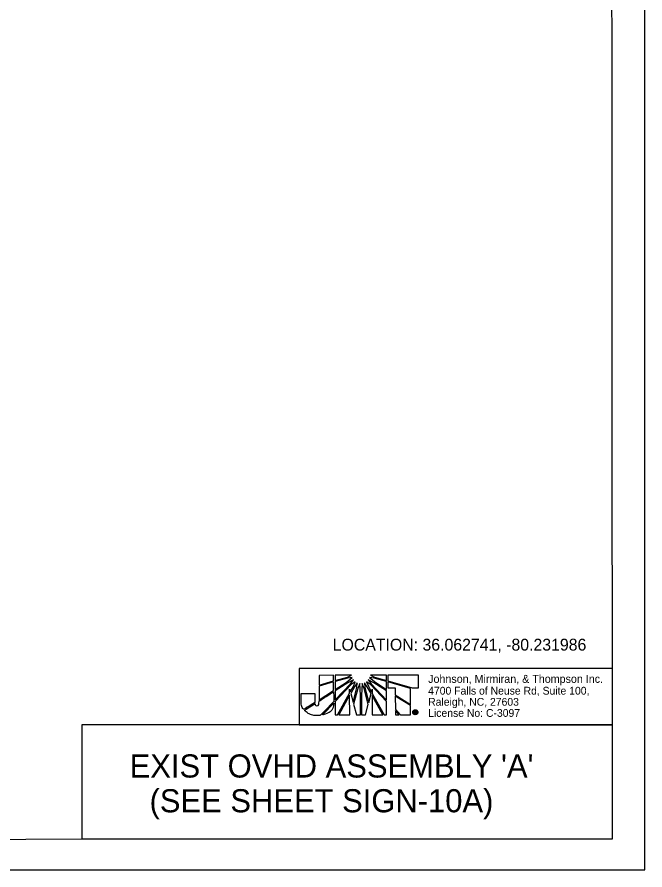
# Model space of a CAD drawing. Extents: x 1726790 to 1728895, y 539219 to 541550.
# Drawn here: x 1727517.9 to 1727598.1, y 539383.1 to 539492 of the extents above; entities that cross this region are included whole.
import ezdxf

# ---------------------------------------------------------------- set-up
doc = ezdxf.new("R2010")
doc.units = 0
for name, color, linetype in [('Default', 7, 'Continuous'), ('DEV BORDER CELL', 7, 'Continuous'), ('Overhead Sheet Border', 7, 'Continuous'), ('Overhead Sheet Box', 7, 'Continuous'), ('Overhead Sheet Text', 7, 'Continuous'), ('Sheet Plot Border Outside CELL', 7, 'Continuous'), ('Sheet Sticker Exception Certification CELL', 7, 'Continuous')]:
    doc.layers.add(name, color=color, linetype=linetype)

msp = doc.modelspace()

# ---------------------------------------------------------------- linework, layer by layer
at = {"layer": 'Default'}
for p, q in [((1727558.32, 539407.99), (1727556.45, 539407.98)), ((1727556.45, 539407.98), (1727556.45, 539406.74)), ((1727558.32, 539407.26), (1727558.32, 539407.99)), ((1727560.62, 539408), (1727558.52, 539408)), ((1727558.52, 539408), (1727558.52, 539407.33)), ((1727558.52, 539407.33), (1727560.09, 539407.76)), ((1727560.09, 539407.61), (1727558.52, 539407.18)), ((1727559.92, 539407.06), (1727560.7, 539407.69)), ((1727560.09, 539407.76), (1727560.62, 539408)), ((1727560.7, 539407.69), (1727560.09, 539407.61)), ((1727562.9, 539407.69), (1727563.69, 539407.05)), ((1727563.48, 539407.62), (1727562.9, 539407.69)), ((1727565.09, 539407.99), (1727563.01, 539408)), ((1727563.01, 539408), (1727563.53, 539407.75)), ((1727565.09, 539407.18), (1727563.48, 539407.62)), ((1727563.53, 539407.75), (1727565.09, 539407.32)), ((1727565.09, 539407.32), (1727565.09, 539407.99)), ((1727569.17, 539408.01), (1727565.23, 539408)), ((1727565.23, 539408), (1727565.23, 539407.28)), ((1727569.17, 539406.39), (1727569.17, 539408.01)), ((1727556.45, 539406.74), (1727558.32, 539407.26)), ((1727558.32, 539407.13), (1727556.45, 539406.6)), ((1727556.45, 539406.6), (1727556.45, 539404.85)), ((1727558.32, 539406.04), (1727558.32, 539407.13)), ((1727558.52, 539407.18), (1727558.52, 539406.17)), ((1727558.52, 539406.17), (1727559.92, 539407.06)), ((1727560.14, 539407.04), (1727558.52, 539406)), ((1727558.52, 539404.84), (1727560.49, 539406.89)), ((1727560.57, 539406.79), (1727558.52, 539404.64)), ((1727560.85, 539407.4), (1727560.14, 539407.04)), ((1727560.45, 539405.86), (1727560.84, 539406.57)), ((1727560.49, 539406.89), (1727560.85, 539407.4)), ((1727560.97, 539406.53), (1727560.5, 539405.68)), ((1727561.07, 539407.17), (1727560.57, 539406.79)), ((1727560.84, 539406.57), (1727561.07, 539407.17)), ((1727561.34, 539407.01), (1727560.97, 539406.53)), ((1727561.29, 539406.43), (1727561.34, 539407.01)), ((1727561.65, 539406.92), (1727561.39, 539406.32)), ((1727561.73, 539405.45), (1727561.65, 539406.92)), ((1727561.96, 539406.92), (1727561.86, 539405.45)), ((1727562.2, 539406.32), (1727561.96, 539406.92)), ((1727562.26, 539407.01), (1727562.32, 539406.41)), ((1727562.62, 539406.53), (1727562.26, 539407.01)), ((1727562.52, 539407.17), (1727562.75, 539406.58)), ((1727563.02, 539406.79), (1727562.52, 539407.17)), ((1727563.1, 539405.65), (1727562.62, 539406.53)), ((1727562.74, 539407.4), (1727563.1, 539406.88)), ((1727563.46, 539407.04), (1727562.74, 539407.4)), ((1727562.75, 539406.58), (1727563.15, 539405.83)), ((1727565.08, 539404.62), (1727563.02, 539406.79)), ((1727563.1, 539406.88), (1727565.08, 539404.82)), ((1727565.07, 539406.02), (1727563.46, 539407.04)), ((1727563.69, 539407.05), (1727565.07, 539406.19)), ((1727565.07, 539406.19), (1727565.09, 539407.18)), ((1727565.23, 539407.28), (1727565.23, 539407.26)), ((1727565.23, 539407.26), (1727568.33, 539406.39)), ((1727565.23, 539407.15), (1727565.23, 539407.13)), ((1727568.13, 539406.32), (1727565.23, 539407.15)), ((1727565.23, 539407.13), (1727565.23, 539406.38)), ((1727556.45, 539404.85), (1727558.32, 539406.04)), ((1727558.52, 539406), (1727558.52, 539404.84)), ((1727558.83, 539402.94), (1727560.36, 539405.7)), ((1727560.36, 539405.44), (1727558.98, 539402.94)), ((1727560.36, 539405.7), (1727560.36, 539406.2)), ((1727560.36, 539406.2), (1727560.45, 539405.86)), ((1727560.37, 539402.94), (1727560.36, 539405.44)), ((1727560.5, 539405.68), (1727560.8, 539404.56)), ((1727560.8, 539404.56), (1727561.29, 539406.43)), ((1727561.39, 539406.32), (1727560.87, 539404.3)), ((1727561.73, 539402.95), (1727561.73, 539405.45)), ((1727561.86, 539405.45), (1727561.86, 539402.95)), ((1727562.74, 539404.27), (1727562.2, 539406.32)), ((1727562.32, 539406.41), (1727562.81, 539404.52)), ((1727562.81, 539404.52), (1727563.1, 539405.65)), ((1727563.15, 539405.83), (1727563.25, 539406.2)), ((1727563.25, 539406.2), (1727563.25, 539405.66)), ((1727563.25, 539405.66), (1727564.75, 539402.94)), ((1727564.59, 539402.95), (1727563.25, 539405.39)), ((1727563.25, 539405.39), (1727563.25, 539402.95)), ((1727565.08, 539404.82), (1727565.07, 539406.02)), ((1727565.23, 539406.38), (1727566.19, 539406.38)), ((1727566.19, 539406.38), (1727566.19, 539405.48)), ((1727566.19, 539405.48), (1727568.13, 539404.25)), ((1727568.13, 539404.25), (1727568.13, 539406.32)), ((1727568.33, 539406.39), (1727569.17, 539406.39)), ((1727558.52, 539404.64), (1727558.52, 539402.94)), ((1727560.87, 539404.3), (1727561.22, 539402.95)), ((1727565.08, 539402.94), (1727565.08, 539404.62)), ((1727566.19, 539405.33), (1727566.2, 539403.65)), ((1727568.13, 539404.11), (1727566.19, 539405.33)), ((1727562.38, 539402.95), (1727562.74, 539404.27)), ((1727566.2, 539403.65), (1727566.87, 539402.95)), ((1727566.68, 539402.95), (1727566.2, 539403.47)), ((1727566.2, 539403.47), (1727566.2, 539402.95)), ((1727568.14, 539402.95), (1727568.13, 539404.11)), ((1727568.63, 539403.12), (1727568.63, 539403.41)), ((1727568.63, 539403.41), (1727568.75, 539403.41)), ((1727568.75, 539403.36), (1727568.69, 539403.36)), ((1727568.69, 539403.36), (1727568.69, 539403.29)), ((1727568.69, 539403.29), (1727568.75, 539403.29)), ((1727568.75, 539403.24), (1727568.69, 539403.24)), ((1727568.69, 539403.24), (1727568.69, 539403.12)), ((1727568.75, 539403.58), (1727568.75, 539403.52)), ((1727568.75, 539403.52), (1727568.75, 539403.58)), ((1727568.75, 539403.41), (1727568.75, 539403.36)), ((1727568.75, 539403.36), (1727568.75, 539403.41)), ((1727568.75, 539403.41), (1727568.76, 539403.41)), ((1727568.75, 539403.36), (1727568.75, 539403.36)), ((1727568.75, 539403.29), (1727568.75, 539403.24)), ((1727568.75, 539403.24), (1727568.75, 539403.29)), ((1727568.75, 539403.29), (1727568.75, 539403.29)), ((1727568.75, 539403.24), (1727568.75, 539403.24)), ((1727558.52, 539402.94), (1727558.83, 539402.94)), ((1727558.98, 539402.94), (1727560.37, 539402.94)), ((1727561.22, 539402.95), (1727561.73, 539402.95)), ((1727561.86, 539402.95), (1727562.38, 539402.95)), ((1727563.25, 539402.95), (1727564.59, 539402.95)), ((1727564.75, 539402.94), (1727565.08, 539402.94)), ((1727566.2, 539402.95), (1727566.68, 539402.95)), ((1727566.87, 539402.95), (1727568.14, 539402.95)), ((1727568.69, 539403.12), (1727568.63, 539403.12)), ((1727568.75, 539403.01), (1727568.75, 539402.95)), ((1727568.75, 539402.95), (1727568.75, 539403.01)), ((1727568.75, 539403.01), (1727568.75, 539403.01)), ((1727568.75, 539402.95), (1727568.75, 539402.95))]:
    msp.add_line(p, q, dxfattribs=at)
msp.add_lwpolyline([(1727553.92, 539401.65), (1727593.92, 539401.65), (1727593.92, 539408.87), (1727553.92, 539408.87)], close=True, dxfattribs=at)
for points in [[(1727556.45, 539406.74), (1727558.32, 539407.26), (1727558.32, 539407.99), (1727556.45, 539407.98), (1727556.45, 539406.74)], [(1727560.09, 539407.76), (1727560.62, 539408), (1727558.52, 539408), (1727558.52, 539407.33), (1727560.09, 539407.76)], [(1727558.52, 539407.18), (1727558.52, 539406.17), (1727559.92, 539407.06), (1727560.7, 539407.69), (1727560.09, 539407.61), (1727558.52, 539407.18)], [(1727562.9, 539407.69), (1727563.69, 539407.05), (1727565.07, 539406.19), (1727565.09, 539407.18), (1727563.48, 539407.62), (1727562.9, 539407.69)], [(1727563.53, 539407.75), (1727565.09, 539407.32), (1727565.09, 539407.99), (1727563.01, 539408), (1727563.53, 539407.75)], [(1727569.17, 539408.01), (1727565.23, 539408), (1727565.23, 539407.28), (1727565.23, 539407.26), (1727568.33, 539406.39), (1727569.17, 539406.39), (1727569.17, 539408.01)], [(1727556.45, 539404.85), (1727558.32, 539406.04), (1727558.32, 539407.13), (1727556.45, 539406.6), (1727556.45, 539404.85)], [(1727558.52, 539406), (1727558.52, 539404.84), (1727560.49, 539406.89), (1727560.85, 539407.4), (1727560.14, 539407.04), (1727558.52, 539406)], [(1727561.07, 539407.17), (1727560.57, 539406.79), (1727558.52, 539404.64), (1727558.52, 539402.94), (1727558.83, 539402.94), (1727560.36, 539405.7), (1727560.36, 539406.2), (1727560.45, 539405.86), (1727560.84, 539406.57), (1727561.07, 539407.17)], [(1727561.34, 539407.01), (1727560.97, 539406.53), (1727560.5, 539405.68), (1727560.8, 539404.56), (1727561.29, 539406.43), (1727561.34, 539407.01)], [(1727561.39, 539406.32), (1727560.87, 539404.3), (1727561.22, 539402.95), (1727561.73, 539402.95), (1727561.73, 539405.45), (1727561.65, 539406.92), (1727561.39, 539406.32)], [(1727561.96, 539406.92), (1727561.86, 539405.45), (1727561.86, 539402.95), (1727562.38, 539402.95), (1727562.74, 539404.27), (1727562.2, 539406.32), (1727561.96, 539406.92)], [(1727562.26, 539407.01), (1727562.32, 539406.41), (1727562.81, 539404.52), (1727563.1, 539405.65), (1727562.62, 539406.53), (1727562.26, 539407.01)], [(1727562.52, 539407.17), (1727562.75, 539406.58), (1727563.15, 539405.83), (1727563.25, 539406.2), (1727563.25, 539405.66), (1727564.75, 539402.94), (1727565.08, 539402.94), (1727565.08, 539404.62), (1727563.02, 539406.79), (1727562.52, 539407.17)], [(1727562.74, 539407.4), (1727563.1, 539406.88), (1727565.08, 539404.82), (1727565.07, 539406.02), (1727563.46, 539407.04), (1727562.74, 539407.4)], [(1727565.23, 539407.15), (1727565.23, 539407.13), (1727565.23, 539406.38), (1727566.19, 539406.38), (1727566.19, 539405.48), (1727568.13, 539404.25), (1727568.13, 539406.32), (1727565.23, 539407.15)], [(1727558.98, 539402.94), (1727560.37, 539402.94), (1727560.36, 539405.44), (1727558.98, 539402.94)], [(1727563.25, 539402.95), (1727564.59, 539402.95), (1727563.25, 539405.39), (1727563.25, 539402.95)], [(1727566.19, 539405.33), (1727566.2, 539403.65), (1727566.87, 539402.95), (1727568.14, 539402.95), (1727568.13, 539404.11), (1727566.19, 539405.33), (1727566.19, 539405.33)], [(1727566.2, 539402.95), (1727566.2, 539402.95), (1727566.68, 539402.95), (1727566.2, 539403.47), (1727566.2, 539402.95)], [(1727568.87, 539403.19), (1727568.87, 539403.18), (1727568.87, 539403.17), (1727568.87, 539403.16), (1727568.88, 539403.12), (1727568.82, 539403.12)]]:
    msp.add_lwpolyline(points, dxfattribs=at)
for points, degree in [([(1727555.91, 539405.66), (1727555.91, 539405.66), (1727554.18, 539405.66), (1727554.18, 539405.66), (1727554.18, 539405.66), (1727554.18, 539404.57), (1727554.18, 539404.57), (1727554.18, 539404.57), (1727554.18, 539404.46), (1727554.18, 539404.46), (1727554.18, 539404.12), (1727554.29, 539403.85), (1727554.49, 539403.62), (1727554.49, 539403.62), (1727555.92, 539404.49), (1727555.92, 539404.51), (1727555.92, 539404.51), (1727555.91, 539405.66), (1727555.91, 539405.66)], 3), ([(1727556.19, 539404.1), (1727556.07, 539404.1), (1727555.98, 539404.16), (1727555.94, 539404.37), (1727555.94, 539404.37), (1727554.59, 539403.53), (1727554.59, 539403.53), (1727555.01, 539403.1), (1727555.67, 539402.84), (1727556.23, 539402.84), (1727556.37, 539402.84), (1727556.49, 539402.85), (1727556.64, 539402.88), (1727556.64, 539402.88), (1727558.33, 539404.63), (1727558.33, 539404.63), (1727558.33, 539404.63), (1727558.32, 539405.89), (1727558.32, 539405.89), (1727558.32, 539405.89), (1727556.45, 539404.7), (1727556.45, 539404.7), (1727556.45, 539404.22), (1727556.34, 539404.1), (1727556.19, 539404.1)], 3), ([(1727556.19, 539404.1), (1727556.07, 539404.1), (1727555.98, 539404.16), (1727555.94, 539404.37), (1727555.94, 539404.37), (1727554.59, 539403.53), (1727554.59, 539403.53), (1727555.01, 539403.1), (1727555.67, 539402.84), (1727556.23, 539402.84), (1727556.37, 539402.84), (1727556.49, 539402.85), (1727556.64, 539402.88), (1727556.64, 539402.88), (1727558.33, 539404.63), (1727558.33, 539404.63), (1727558.33, 539404.63), (1727558.32, 539405.89), (1727558.32, 539405.89), (1727558.32, 539405.89), (1727556.45, 539404.7), (1727556.45, 539404.7), (1727556.45, 539404.22), (1727556.34, 539404.1), (1727556.19, 539404.1)], 3), ([(1727558.33, 539404.43), (1727558.33, 539404.43), (1727556.87, 539402.92), (1727556.87, 539402.92), (1727557.58, 539403.1), (1727558.29, 539403.57), (1727558.33, 539404.43)], 3), ([(1727568.75, 539402.95), (1727568.66, 539402.95), (1727568.58, 539402.98), (1727568.52, 539403.04), (1727568.46, 539403.1), (1727568.43, 539403.18), (1727568.43, 539403.27), (1727568.43, 539403.36), (1727568.46, 539403.43), (1727568.52, 539403.49), (1727568.58, 539403.55), (1727568.66, 539403.58), (1727568.75, 539403.58)], 3), ([(1727568.75, 539403.52), (1727568.68, 539403.52), (1727568.62, 539403.5), (1727568.57, 539403.45), (1727568.52, 539403.4), (1727568.49, 539403.34), (1727568.49, 539403.27), (1727568.49, 539403.2), (1727568.52, 539403.13), (1727568.57, 539403.09), (1727568.62, 539403.04), (1727568.68, 539403.01), (1727568.75, 539403.01)], 3), ([(1727568.75, 539403.58), (1727568.83, 539403.58), (1727568.91, 539403.55), (1727568.97, 539403.49), (1727569.03, 539403.43), (1727569.07, 539403.36), (1727569.07, 539403.27)], 3), ([(1727568.75, 539403.01), (1727568.82, 539403.01), (1727568.88, 539403.04), (1727568.93, 539403.09), (1727568.98, 539403.14), (1727569, 539403.2), (1727569, 539403.27), (1727569, 539403.34), (1727568.98, 539403.4), (1727568.93, 539403.45), (1727568.88, 539403.5), (1727568.82, 539403.52), (1727568.75, 539403.52)], 3), ([(1727568.75, 539403.29), (1727568.79, 539403.29), (1727568.81, 539403.3), (1727568.81, 539403.33), (1727568.81, 539403.35), (1727568.79, 539403.36), (1727568.75, 539403.36)], 3), ([(1727569.07, 539403.27), (1727569.07, 539403.18), (1727569.03, 539403.1), (1727568.97, 539403.04), (1727568.91, 539402.98), (1727568.84, 539402.95), (1727568.75, 539402.95)], 3), ([(1727568.8, 539403.23), (1727568.79, 539403.23), (1727568.77, 539403.24), (1727568.75, 539403.24)], 2), ([(1727568.76, 539403.41), (1727568.84, 539403.41), (1727568.87, 539403.38), (1727568.87, 539403.33), (1727568.87, 539403.3), (1727568.86, 539403.28), (1727568.84, 539403.26)], 3), ([(1727568.82, 539403.12), (1727568.81, 539403.14), (1727568.81, 539403.16), (1727568.81, 539403.18), (1727568.81, 539403.2), (1727568.81, 539403.22), (1727568.8, 539403.23)], 3), ([(1727568.84, 539403.26), (1727568.86, 539403.25), (1727568.87, 539403.23), (1727568.87, 539403.19)], 2)]:
    msp.add_open_spline(points, degree=degree, dxfattribs=at)
at = {"layer": 'DEV BORDER CELL'}
msp.add_line((1727598.07, 539383.13), (1727598.07, 539383.13), dxfattribs=at)
at = {"layer": 'Overhead Sheet Border'}
msp.add_lwpolyline([(1727593.82, 539596.91), (1727294.08, 539596.75), (1727294.19, 539386.93), (1727593.93, 539387.09)], close=True, dxfattribs=at)
at = {"layer": 'Overhead Sheet Box'}
msp.add_lwpolyline([(1727526.16, 539387.09), (1727593.93, 539387.09), (1727593.93, 539401.65), (1727526.16, 539401.65)], close=True, dxfattribs=at)
at = {"layer": 'Sheet Plot Border Outside CELL'}
msp.add_lwpolyline([(1727598.07, 539602.3), (1727261.51, 539602.3), (1727261.51, 539383.13), (1727598.07, 539383.13)], close=True, dxfattribs=at)

# ---------------------------------------------------------------- texts
at = {"layer": 'Default'}
for s, height, p in [('Johnson, Mirmiran, & Thompson Inc.', 1.0222, (1727570.39, 539407.02)), ('4700 Falls of Neuse Rd, Suite 100, ', 0.993, (1727570.39, 539405.52)), ('Raleigh, NC, 27603', 0.993, (1727570.39, 539404.1)), ('License No: C-3097', 0.993, (1727570.39, 539402.68))]:
    msp.add_text(s, height=height, dxfattribs=at).set_placement(p)
at = {"layer": 'Overhead Sheet Text'}
msp.add_text('LOCATION: 36.062741, -80.231986', height=1.5128, dxfattribs=at).set_placement((1727558.2, 539411.14))
at = {"layer": 'Sheet Sticker Exception Certification CELL'}
for s, p in [("EXIST OVHD ASSEMBLY 'A'", (1727532.27, 539394.93)), ('(SEE SHEET SIGN-10A)', (1727534.81, 539390.49))]:
    msp.add_text(s, height=2.9545, dxfattribs=at).set_placement(p)

doc.saveas('drawing.dxf')
